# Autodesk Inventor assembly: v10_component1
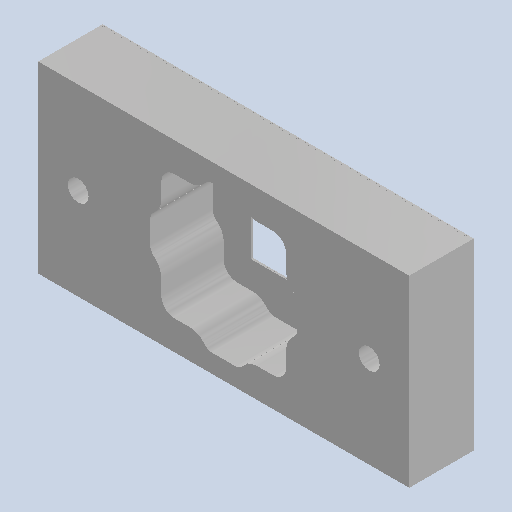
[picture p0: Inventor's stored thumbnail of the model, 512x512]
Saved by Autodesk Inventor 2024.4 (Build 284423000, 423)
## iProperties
Created: 2025-08
Part Number: v10_component1
Document SubType Name: Assembly
Designer: AdminForWorker
Title: v10_component1 v3
Author: AdminForWorker
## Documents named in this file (4)
- c:\worker\convert-fusion-r03-cosv3\tmp\job-1\473\temp\files\ff99e9fd-b84d-4b75-99f6-2e10e07a3986\f5157c92-7066-4fc6-b586-e16ea6a06cac.iam
- c:\worker\convert-fusion-r03-cosv3\tmp\job-1\473\temp\files\ff99e9fd-b84d-4b75-99f6-2e10e07a3986\L2 - PSA.ipt
- c:\worker\convert-fusion-r03-cosv3\tmp\job-1\473\temp\files\ff99e9fd-b84d-4b75-99f6-2e10e07a3986\L1 - ACRYLIC.ipt
- c:\worker\convert-fusion-r03-cosv3\tmp\job-1\473\temp\files\ff99e9fd-b84d-4b75-99f6-2e10e07a3986\L3 - PET.ipt
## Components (3 placed, 3 different names)
1. L2 - PSA:1
2. L1 - ACRYLIC:1
3. L3 - PET:1
